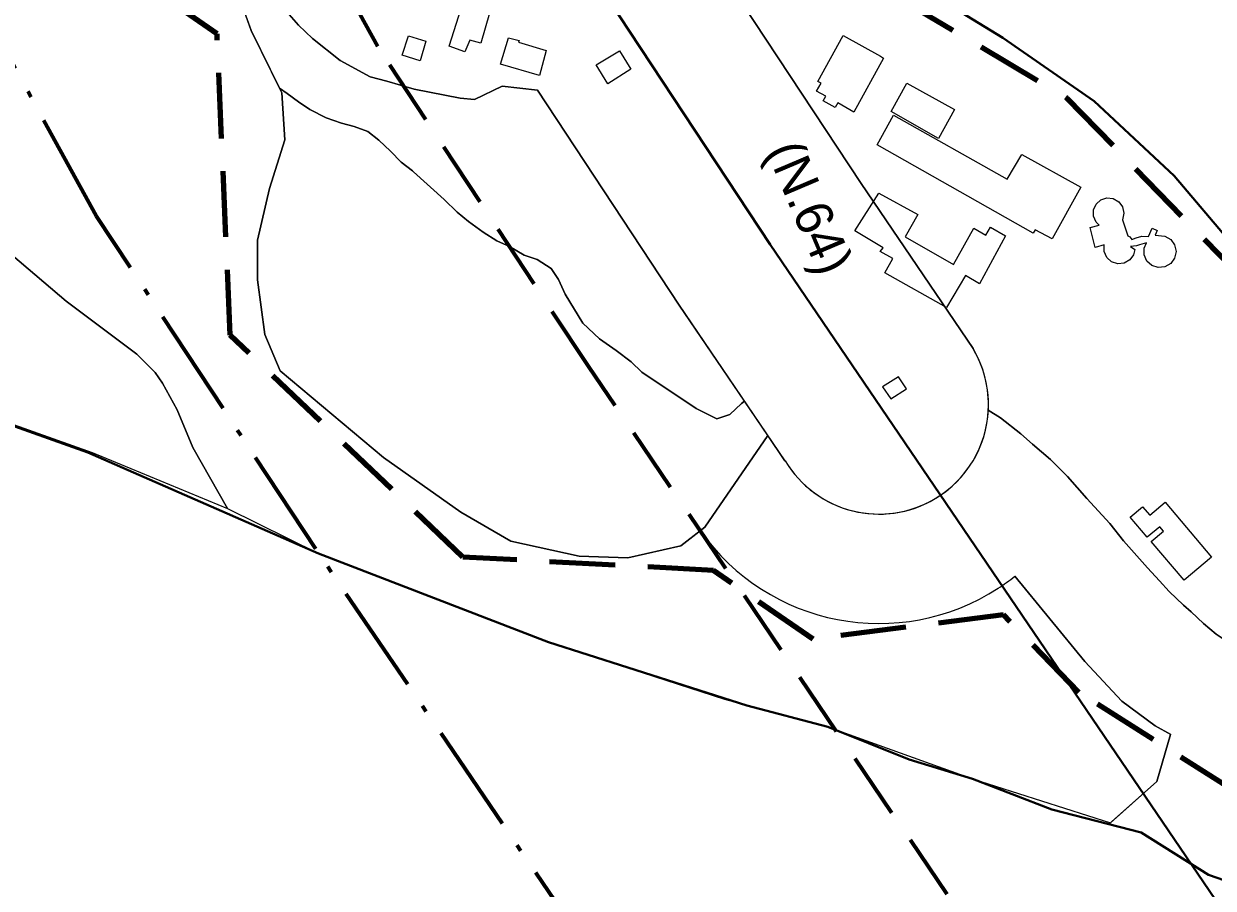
# Model space of a CAD drawing. Extents: x 645880 to 658994, y 884400 to 894744.
# Drawn here: x 658160 to 658704, y 890454 to 890849 of the extents above; entities that cross this region are included whole.
import ezdxf
from ezdxf.enums import TextEntityAlignment as Align

# ---------------------------------------------------------------- set-up
doc = ezdxf.new("R2010")
doc.units = 0
doc.header["$LTSCALE"] = 10
doc.linetypes.add('DOT_DASHED', pattern=[7.7, 5, -1.2, 0.3, -1.2])
doc.linetypes.add('MEDIUM_DASHED', pattern=[4.5, 3, -1.5])
for name, color, linetype, lineweight in [('1', 7, 'Continuous', 25), ('15', 7, 'MEDIUM_DASHED', 100), ('17', 7, 'Continuous', 25), ('29', 7, 'Continuous', 25), ('45', 7, 'Continuous', 25), ('55', 7, 'Continuous', 25), ('59', 7, 'Continuous', 40)]:
    doc.layers.add(name, color=color, linetype=linetype, lineweight=lineweight)
doc.layers.add('60', color=7, linetype='Continuous')

msp = doc.modelspace()

# ---------------------------------------------------------------- linework, layer by layer
at = {"layer": '1'}
msp.add_line((658600.73, 890672.71), (658606.22, 890669.12), dxfattribs=at)
for points in [[(658739.03, 890473.33), (658756.51, 890523.43), (658765.5, 890521.08), (658769.12, 890537.27), (658774.78, 890569.34), (658776.65, 890596.85), (658762.13, 890660.79), (658748.52, 890696.29), (658734.11, 890723.12), (658711.99, 890748.7), (658685.73, 890779.68), (658649.08, 890813.91), (658607.39, 890842.81), (658572.51, 890864.27), (658498.11, 890905.65), (658476.25, 890915.58), (658449.03, 890925.07), (658444.85, 890926.07)], [(658444.85, 890926.07), (658450.17, 890916.4), (658542.57, 890776.22), (658593.81, 890700.86), (658593.73, 890700.81)], [(658606.22, 890669.12), (658615.65, 890661.8), (658620.95, 890657.21), (658629.2, 890650.2), (658636.86, 890642.4), (658645.78, 890632.36), (658656.28, 890620.85), (658662.52, 890612.9)], [(658662.52, 890612.9), (658668.56, 890606.13), (658673.54, 890600.57), (658678.91, 890594.73), (658683.33, 890589.88), (658689.89, 890583.59), (658693.41, 890580.53), (658699.14, 890575.22), (658704.92, 890570.34), (658710.44, 890566.72), (658716.62, 890563.17), (658722.06, 890559.71), (658727.26, 890556.49), (658732.2, 890552.61), (658736.08, 890549.32), (658738.88, 890545.93), (658740.77, 890542.72), (658743.25, 890537.52), (658743.36, 890531.77), (658744.1, 890526.67), (658734.42, 890511.87), (658724.66, 890480.11), (658727.49, 890478.43), (658739.03, 890473.33)]]:
    msp.add_lwpolyline(points, dxfattribs=at)
for points in [[(658326.23, 890873.08), (658329.15, 890882.79), (658377.03, 890869.01), (658368.77, 890840.39), (658363.78, 890841.73), (658361.37, 890836.44), (658354.31, 890839.03), (658361.89, 890863.13)], [(658332.82, 890834.96), (658335.65, 890843.74), (658343.67, 890841.26), (658340.95, 890832.28)], [(658395.54, 890825.64), (658377.69, 890830.72), (658381.39, 890842.76), (658386.19, 890841.54), (658385.95, 890840.8), (658398.56, 890837)], [(658522.79, 890822.84), (658534.42, 890843.8), (658551.49, 890834.38), (658552.75, 890833.46), (658539.22, 890808.84), (658531.87, 890813.14), (658530.64, 890811.04), (658525.25, 890814.06), (658526.4, 890816.16), (658522.19, 890818.5), (658524.25, 890822.04)], [(658426.77, 890821.82), (658421.5, 890830.4), (658432.09, 890836.86), (658437.32, 890828.48)], [(658556.25, 890809.14), (658563.42, 890822.04), (658585.22, 890810.02), (658577.95, 890796.84)], [(658549.85, 890793.95), (658557.35, 890807.45), (658609.34, 890778.21), (658615.98, 890789.47), (658643.07, 890774.51), (658629.98, 890751.01), (658622.21, 890755.13), (658621.26, 890753.61)], [(658539.69, 890754.6), (658550.64, 890771.78), (658568.52, 890762.11), (658562.69, 890751.83), (658584.86, 890739.31), (658594.06, 890755.91), (658599.58, 890752.59), (658601.74, 890756.27), (658608.52, 890752.37), (658596.62, 890730.46), (658590.36, 890734.16), (658581.6, 890719.63), (658553.41, 890735.47), (658557.12, 890742.01), (658551.36, 890745.15), (658552.72, 890746.88)], [(658653.69, 890748.18), (658649.63, 890747.02), (658647.27, 890756.2), (658651.44, 890757.26), (658649.96, 890758.6), (658648.78, 890761.26), (658648.78, 890764.18), (658649.96, 890766.84), (658652.13, 890768.8), (658654.91, 890769.7), (658657.81, 890769.38), (658660.33, 890767.92), (658662.05, 890765.56), (658662.66, 890762.72), (658662.01, 890759.68), (658664.47, 890752.38), (658665.38, 890751.88), (658666.26, 890750.68), (658668.31, 890751.4), (658670.91, 890752.2), (658673.94, 890752.02), (658675.62, 890755.82), (658677.96, 890754.74), (658676.97, 890752.64), (658681.45, 890752.16), (658684.1, 890750.64), (658685.9, 890748.16), (658686.54, 890745.16), (658685.9, 890742.16), (658684.1, 890739.68), (658681.45, 890738.14), (658678.4, 890737.82), (658675.48, 890738.78), (658673.21, 890740.82), (658671.96, 890743.62), (658671.96, 890746.68), (658673.03, 890749.18), (658669.85, 890748.2), (658668.5, 890747.7), (658665.7, 890747.4), (658667.63, 890746.14), (658667.11, 890743.72), (658665.38, 890741.34), (658662.82, 890739.86), (658659.89, 890739.56), (658657.08, 890740.46), (658654.89, 890742.44), (658653.69, 890745.14)], [(658552.34, 890683.32), (658556.16, 890677.9), (658563.26, 890682.36), (658559.64, 890687.9)], [(658690.27, 890594.92), (658675.23, 890612.68), (658680.82, 890617.42), (658679.09, 890619.42), (658673.37, 890614.58), (658665.59, 890623.78), (658671.23, 890628.54), (658674.57, 890624.68), (658681.6, 890630.62), (658702.81, 890605.52)]]:
    msp.add_lwpolyline(points, close=True, dxfattribs=at)
msp.add_arc((658550.8, 890675.19), 50, 357.1479, 30.821, dxfattribs=at)
at = {"layer": '15'}
msp.add_lwpolyline([(658297.51, 891502.22), (658330.3, 891246.22), (658327.72, 891183.18), (658338.55, 891136.81), (658353.44, 891095.71), (658449.21, 890955.48), (658420.28, 890931.68), (658481.44, 890907.81), (658636.65, 890815.27), (658732.37, 890716.91), (658771.82, 890588.13), (658747.24, 890482.65), (658726.56, 890461.94), (658714.04, 890498.12), (658642.13, 890543.72), (658607.69, 890579.19), (658520.59, 890568.04), (658475.02, 890599.46), (658360.56, 890605.54), (658254.22, 890706.88), (658248.14, 890844.7), (658184.33, 890889.29), (658123.56, 891003.8)], dxfattribs=at)
at = {"layer": '17'}
for points in [[(658324.2, 890651.02), (658277, 890690.61), (658270.06, 890707.27), (658266.59, 890732.27), (658266.59, 890750.33), (658272.14, 890773.94), (658279.08, 890796.16), (658277.7, 890817.69), (658263.82, 890846.16), (658260.52, 890855.19)], [(658095.37, 890800.73), (658147.28, 890749.45), (658179.18, 890722.55), (658211.42, 890698.32), (658219.85, 890689.89), (658223.26, 890685.08), (658229.88, 890672.83), (658237.08, 890655.67), (658252.93, 890627.77), (658294.53, 890607.14), (658399.64, 890566.7), (658480.13, 890540.67), (658527.41, 890528.03), (658593.56, 890504.29), (658656.52, 890484.17)], [(658069.72, 890696.37), (658191.14, 890653.3), (658252.93, 890627.77), (658237.08, 890655.67), (658229.88, 890672.83), (658223.26, 890685.08), (658219.85, 890689.89), (658211.42, 890698.32), (658179.18, 890722.55), (658147.28, 890749.45)], [(658469.04, 890617.6), (658460.23, 890610.75), (658435.94, 890605.19), (658413.73, 890605.89), (658382.5, 890612.83), (658359.59, 890626.02), (658324.2, 890651.02)], [(658656.52, 890484.17), (658677.71, 890502.99), (658684.06, 890524.41), (658684.12, 890524.52), (658676.97, 890528.46), (658661.79, 890539.65), (658644.88, 890557.79), (658612.82, 890596.75)]]:
    msp.add_lwpolyline(points, dxfattribs=at)
for start, end in [(215.1624, 302.9917), (302.9917, 308.336)]:
    msp.add_arc((658550.8, 890675.19), 100, start, end, dxfattribs=at)
at = {"layer": '29'}
msp.add_line((658369.83, 890753.97), (658376.12, 890750.06), dxfattribs=at)
for points in [[(658318.11, 890824.92), (658304.37, 890832.43), (658291.73, 890842.51), (658285.44, 890848.58), (658280.03, 890854.64), (658274.77, 890860.54), (658268.2, 890871.38), (658262.4, 890884.41)], [(658251.71, 890879.33), (658263.82, 890846.16), (658276.67, 890819.81), (658280.14, 890817.31), (658285.35, 890813.58), (658290.57, 890810.05), (658298.1, 890806.25), (658305.01, 890803.78), (658310.76, 890802.35)], [(658285.35, 890813.58), (658280.14, 890817.31), (658276.67, 890819.81), (658277.7, 890817.69)], [(658338.26, 890819.42), (658325.79, 890823.01), (658318.11, 890824.92)], [(658442.34, 890690.05), (658467.21, 890673.37), (658476.58, 890668.78), (658482.63, 890670.75), (658487.87, 890675.79), (658489.28, 890676.74), (658459.47, 890720.59), (658394.66, 890818.91), (658378.42, 890820.76), (658365.81, 890814.65), (658359.24, 890815.26), (658338.26, 890819.42)], [(658277.7, 890817.69), (658279.08, 890796.16), (658272.14, 890773.94), (658266.59, 890750.33), (658266.59, 890732.27), (658270.06, 890707.27), (658277, 890690.61), (658324.2, 890651.02), (658359.59, 890626.02)], [(658298.1, 890806.25), (658290.57, 890810.05), (658285.35, 890813.58)], [(658322.07, 890795.98), (658317.01, 890799.98), (658310.76, 890802.35), (658305.01, 890803.78), (658298.1, 890806.25)], [(658310.76, 890802.35), (658317.01, 890799.98), (658322.07, 890795.98), (658327.42, 890791.08), (658332.37, 890785.95), (658337.56, 890781.98), (658337.9, 890781.56), (658352.05, 890768.92), (658357.94, 890763.17)], [(658332.37, 890785.95), (658327.42, 890791.08), (658322.07, 890795.98)], [(658376.12, 890750.06), (658369.83, 890753.97), (658363.04, 890758.93), (658357.94, 890763.17), (658352.05, 890768.92), (658337.9, 890781.56), (658337.56, 890781.98), (658332.37, 890785.95)], [(658357.94, 890763.17), (658363.04, 890758.93), (658369.83, 890753.97)], [(658376.12, 890750.06), (658381.83, 890747.44), (658388.54, 890743.54), (658394.56, 890741.53)], [(658388.54, 890743.54), (658381.83, 890747.44), (658376.12, 890750.06)], [(658404.27, 890732.41), (658400.96, 890737.37), (658394.56, 890741.53), (658388.54, 890743.54)], [(658394.56, 890741.53), (658400.96, 890737.37), (658404.27, 890732.41), (658407.26, 890725.63)], [(658430.6, 890699.87), (658423.01, 890705.28), (658415.29, 890712.39), (658407.26, 890725.63), (658404.27, 890732.41)], [(658407.26, 890725.63), (658415.29, 890712.39), (658423.01, 890705.28), (658430.6, 890699.87), (658437.4, 890694.69), (658442.34, 890690.05)], [(658476.58, 890668.78), (658467.21, 890673.37), (658442.34, 890690.05), (658437.4, 890694.69), (658430.6, 890699.87)], [(658359.59, 890626.02), (658382.5, 890612.83), (658413.73, 890605.89), (658435.94, 890605.19), (658460.23, 890610.75), (658471.13, 890619.23), (658499.89, 890661.13), (658489.28, 890676.74)], [(658489.28, 890676.74), (658487.87, 890675.79), (658482.63, 890670.75), (658476.58, 890668.78)]]:
    msp.add_lwpolyline(points, dxfattribs=at)
at = {"layer": '45'}
msp.add_line((658593.82, 890700.66), (658593.81, 890700.86), dxfattribs=at)
at = {"layer": '45', "lineweight": 40}
msp.add_lwpolyline([(658715.27, 890433.27), (658501.02, 890748.41), (658407.33, 890890.55), (658327.88, 891034.96), (658274.79, 891241.39)], dxfattribs=at)
at = {"layer": '45', "linetype": 'MEDIUM_DASHED', "lineweight": 70}
msp.add_lwpolyline([(658632.57, 890377.05), (658417.92, 890692.78), (658321.64, 890838.85), (658234.18, 890997.82), (658177.94, 891216.48)], dxfattribs=at)
at = {"layer": '45', "linetype": 'DOT_DASHED', "lineweight": 70}
msp.add_lwpolyline([(658508.52, 890292.72), (658293.27, 890609.33), (658193.1, 890761.3), (658093.63, 890942.11), (658032.74, 891178.84)], dxfattribs=at)
at = {"layer": '45'}
for points in [[(658293.69, 890993.12), (658350.51, 890888.68), (658326.4, 890881.71), (658299.61, 890865.63), (658285.68, 890857.59), (658280.03, 890854.64), (658285.44, 890848.58), (658291.73, 890842.51), (658304.37, 890832.43), (658318.11, 890824.92), (658325.79, 890823.01), (658338.26, 890819.42), (658359.24, 890815.26)], [(658593.81, 890700.86), (658542.57, 890776.22), (658450.17, 890916.4), (658444.46, 890926.78), (658435.52, 890930.14), (658420.44, 890933.87), (658433.45, 890946.79)], [(658359.24, 890815.26), (658365.81, 890814.65), (658378.42, 890820.76), (658394.66, 890818.91), (658459.47, 890720.59), (658507.78, 890649.53), (658507.88, 890649.54)]]:
    msp.add_lwpolyline(points, dxfattribs=at)
for start, end in [(300.821, 30.6243), (210.8689, 300.821)]:
    msp.add_arc((658550.8, 890675.19), 50, start, end, dxfattribs=at)
at = {"layer": '55'}
for points in [[(658662.52, 890612.9), (658656.28, 890620.85), (658645.78, 890632.36), (658636.86, 890642.4), (658629.2, 890650.2), (658620.95, 890657.21), (658615.65, 890661.8), (658606.22, 890669.12), (658600.73, 890672.71)], [(658499.89, 890661.13), (658471.13, 890619.23), (658469.04, 890617.6)], [(658507.86, 890649.57), (658507.78, 890649.53), (658499.89, 890661.13)], [(658739.03, 890473.33), (658727.49, 890478.43), (658724.66, 890480.11), (658734.42, 890511.87), (658744.1, 890526.67), (658743.36, 890531.77), (658743.25, 890537.52), (658740.77, 890542.72), (658738.88, 890545.93), (658736.08, 890549.32), (658732.2, 890552.61), (658727.26, 890556.49), (658722.06, 890559.71), (658716.62, 890563.17), (658710.44, 890566.72), (658704.92, 890570.34), (658699.14, 890575.22), (658693.41, 890580.53), (658689.89, 890583.59), (658683.33, 890589.88), (658678.91, 890594.73), (658673.54, 890600.57), (658668.56, 890606.13), (658662.52, 890612.9)], [(658612.82, 890596.75), (658644.88, 890557.79), (658661.79, 890539.65), (658676.97, 890528.46), (658684.12, 890524.52), (658684.06, 890524.41), (658677.71, 890502.99), (658655.78, 890483.51), (658670.58, 890479.68), (658701.39, 890460.34), (658726.76, 890451.55), (658753.94, 890459.46), (658759.82, 890493.58), (658765.5, 890521.08)]]:
    msp.add_lwpolyline(points, dxfattribs=at)
for radius, start, end in [(50, 301.2089, 357.1479), (50, 210.8228, 301.2089), (100, 215.1624, 302.9917), (100, 302.9917, 308.336)]:
    msp.add_arc((658550.8, 890675.19), radius, start, end, dxfattribs=at)
at = {"layer": '59'}
for points in [[(658330, 891159.83), (658351.27, 891093.81), (658409.97, 891009.63), (658443.46, 890956.73), (658420.44, 890933.87), (658435.52, 890930.14), (658449.03, 890925.07), (658476.25, 890915.58), (658498.11, 890905.65), (658513.63, 890897.7), (658572.51, 890864.27), (658607.39, 890842.81), (658649.08, 890813.91), (658685.73, 890779.68), (658711.99, 890748.7)], [(658726.76, 890451.55), (658701.39, 890460.34), (658670.58, 890479.68), (658629.8, 890490.23), (658593.56, 890504.29), (658564.56, 890513.08), (658527.41, 890528.03), (658490.26, 890537.69), (658399.64, 890566.7), (658294.53, 890607.14), (658189.15, 890653.36), (658067.73, 890696.43)]]:
    msp.add_lwpolyline(points, dxfattribs=at)

# ---------------------------------------------------------------- texts
at = {"layer": '60'}
msp.add_text('(N.64)', height=17, rotation=293.006, dxfattribs=at).set_placement((658511.38, 890762.1), align=Align.CENTER)

doc.saveas('drawing.dxf')
